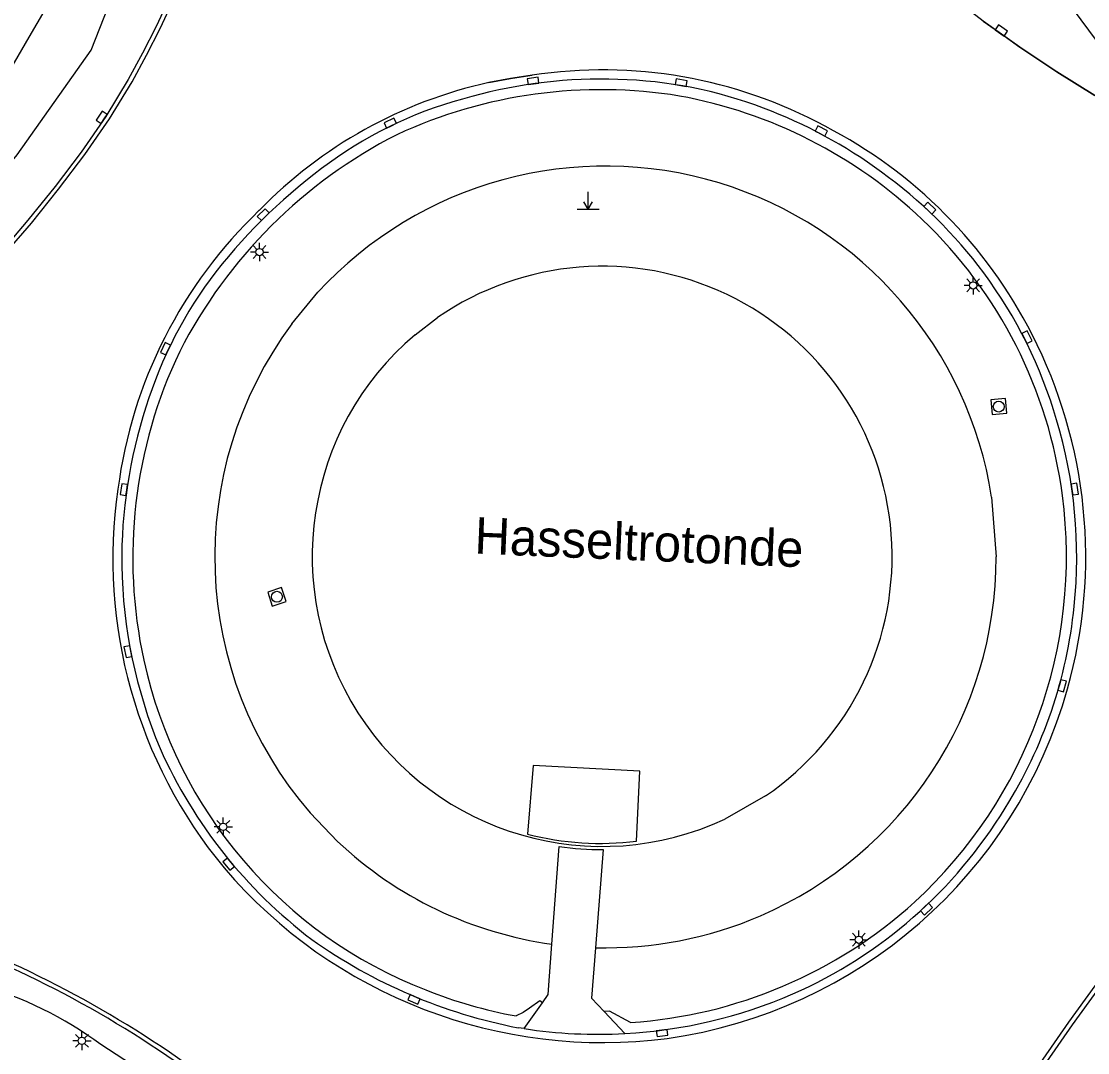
# Model space of a CAD drawing. Extents: x 132573 to 132944, y 398226 to 398676.
# Drawn here: x 132717.2 to 132790.1, y 398529.9 to 398600.4 of the extents above; entities that cross this region are included whole.
import ezdxf

# ---------------------------------------------------------------- set-up
doc = ezdxf.new("R2010")
doc.units = 0
for name, color, linetype in [('gg-anno-openbare ruimte label', 7, 'Continuous'), ('gg-knt-verharding', 7, 'Continuous'), ('gt-grn-groengrens', 7, 'Continuous'), ('gt-symb-kolk', 7, 'Continuous'), ('gt-symb-lichtmast', 7, 'Continuous'), ('gt-symb-markant object', 7, 'Continuous'), ('gt-symb-rioolschacht', 7, 'Continuous'), ('ir-asfa-asfalt arcering', 7, 'Continuous')]:
    doc.layers.add(name, color=color, linetype=linetype)

msp = doc.modelspace()

# ---------------------------------------------------------------- linework, layer by layer
at = {"layer": 'gg-knt-verharding'}
for p, q in [((132753.497, 398537.291), (132753.987, 398543.962)), ((132756.99, 398543.751), (132756.475, 398537.047)), ((132751.597, 398531.515), (132752.843, 398533.274)), ((132757.071, 398532.686), (132758.488, 398531.181)), ((132751.597, 398531.515), (132751.193, 398531.579))]:
    msp.add_line(p, q, dxfattribs=at)
for points in [[(132804.517, 398588.97), (132801.609, 398590.017), (132798.781, 398591.166), (132796.001, 398592.428), (132793.274, 398593.802), (132790.609, 398595.29), (132788.013, 398596.897), (132785.477, 398598.596), (132782.987, 398600.362), (132781.584, 398601.429), (132780.223, 398602.55), (132776.258, 398606.047), (132773.651, 398608.506), (132771.328, 398610.934), (132769.16, 398613.439), (132767.11, 398616.043), (132765.185, 398618.739), (132764.27, 398620.121), (132763.109, 398622.093)], [(132730.572, 398610.916), (132729.337, 398607.173), (132728.34, 398604.388), (132727.206, 398601.656), (132726.438, 398600.001), (132725.517, 398598.174), (132724.533, 398596.379), (132722.993, 398593.854), (132721.312, 398591.421), (132719.528, 398589.063), (132717.677, 398586.758), (132716.062, 398584.871), (132714.384, 398583.039), (132712.637, 398581.273), (132710.815, 398579.584), (132708.924, 398577.973), (132706.969, 398576.441), (132704.953, 398574.989), (132702.88, 398573.621), (132700.49, 398572.115), (132698.154, 398570.84)], [(132749.187, 398596.167), (132750.659, 398596.453), (132752.149, 398596.669)], [(132814.41, 398558.002), (132813.19, 398557.181), (132810.42, 398555.136), (132807.72, 398553), (132805.071, 398550.8), (132803.779, 398549.661), (132802.542, 398548.463), (132800.438, 398546.23), (132798.437, 398543.904), (132795.544, 398540.327), (132792.7, 398536.71), (132790.857, 398534.259), (132789.059, 398531.775), (132787.312, 398529.255), (132786.355, 398527.786)], [(132759.288, 398544.332), (132759.51, 398549.111), (132752.217, 398549.491), (132751.83, 398544.808)], [(132752.843, 398533.274), (132753.244, 398533.841), (132753.497, 398537.291)], [(132756.475, 398537.047), (132756.21, 398533.601), (132757.071, 398532.686)], [(132752.843, 398533.274), (132752.672, 398533.406), (132751.97, 398532.907), (132751.522, 398532.616), (132751.046, 398532.384)], [(132758.876, 398531.937), (132757.44, 398532.721), (132757.071, 398532.686)]]:
    msp.add_lwpolyline(points, dxfattribs=at)
for centre, radius, start, end in [((132756.963, 398565.093), 31.941, 61.55928, 98.66902), ((132756.793, 398563.614), 32.79, 87.86658, 105.50115), ((132757.247, 398566.313), 30.078, 69.13326, 88.53946), ((132755.885, 398565.654), 31.239, 102.38087, 135.79032), ((132756.864, 398562.478), 33.205, 80.72629, 114.86044), ((132754.788, 398567.933), 28.103, 103.91356, 125.9423), ((132756.378, 398563.229), 32.548, 46.42276, 79.66833), ((132756.131, 398562.938), 33.629, 53.74079, 69.4045), ((132757.206, 398564.149), 32.662, 26.95424, 62.72263), ((132758.332, 398562.293), 34.014, 116.97416, 152.91388), ((132761.111, 398559.079), 38.983, 125.82863, 141.69357), ((132757.041, 398563.771), 32.42, 36.74989, 54.1663), ((132755.558, 398564.266), 31.996, 133.59843, 172.59731), ((132756.947, 398563.827), 31.722, 7.47814, 46.42253), ((132754.355, 398565.072), 29.971, 142.67745, 162.6865), ((132757.225, 398564.118), 32.066, 16.30578, 36.44965), ((132756.672, 398563.749), 33.319, 344.32764, 27.15166), ((132757.447, 398563.676), 32.606, 154.37004, 192.37204), ((132758.321, 398563.462), 34.238, 162.08964, 180.4849), ((132756.95, 398563.784), 32.425, 353.96761, 16.73652), ((132756.554, 398563.601), 33.074, 171.67866, 219.6413), ((132756.62, 398563.783), 32.052, 312.57762, 7.48168), ((132758.237, 398563.806), 34.159, 181.06369, 202.62542), ((132757.564, 398563.492), 31.784, 327.87595, 354.37362), ((132756.244, 398563.398), 31.371, 192.34614, 248.76257), ((132756.768, 398563.757), 33.229, 277.98264, 344.26876), ((132757.191, 398564.248), 33.373, 204.01756, 232.94132), ((132756.99, 398563.356), 32.2, 293.76374, 328.62376), ((132756.79, 398563.859), 19.686, 255.40659, 277.28961), ((132756.863, 398563.421), 19.671, 261.59223, 270.36942), ((132756.974, 398564.606), 34.042, 220.49094, 277.44088), ((132756.775, 398563.908), 32.04, 273.76027, 312.22201), ((132685.962, 398469.092), 73.258, 52.01355, 69.15229), ((132758.044, 398567.112), 36.188, 234.59652, 259.08765), ((132756.777, 398563.923), 32.055, 248.21425, 259.70114), ((132756.655, 398564.662), 33.532, 273.13325, 293.38841), ((132756.655, 398564.616), 33.485, 261.31219, 273.13802)]:
    msp.add_arc(centre, radius, start, end, dxfattribs=at)
at = {"layer": 'gt-grn-groengrens'}
for p, q in [((132735.719, 398579.683), (132737.501, 398581.836)), ((132744.145, 398578.936), (132745.681, 398580.11)), ((132783.556, 398567.84), (132783.871, 398563.751)), ((132768.1, 398547.418), (132765.324, 398545.836)), ((132738.84, 398544.31), (132736.96, 398546.271))]:
    msp.add_line(p, q, dxfattribs=at)
for points in [[(132706.238, 398585.328), (132700.524, 398580.236), (132698.397, 398578.341), (132698.865, 398576.798), (132699.804, 398575.637), (132706.276, 398580.281), (132713.192, 398586.704), (132716.947, 398591.224), (132721.989, 398598.375), (132723.82, 398603.024), (132724.452, 398604.629), (132723.622, 398605.26), (132721.995, 398604.844), (132719.838, 398602.875), (132717.889, 398599.543), (132717.479, 398598.843), (132714.696, 398594.086), (132708.872, 398587.901), (132706.238, 398585.328)], [(132787.196, 398603.827), (132787.25, 398603.827), (132788.8, 398605.005), (132795.328, 398596.227), (132793.724, 398594.996), (132787.196, 398603.827)]]:
    msp.add_lwpolyline(points, dxfattribs=at)
for centre, radius, start, end in [((132757.159, 398563.751), 26.712, 8.80593, 137.38628), ((132756.936, 398563.795), 19.82, 304.28132, 124.60054), ((132757.157, 398563.75), 26.71, 143.37995, 220.87429), ((132756.931, 398563.791), 19.82, 130.1716, 295.05461), ((132757.158, 398563.751), 26.713, 293.35304, 0.00099), ((132757.157, 398563.747), 26.708, 226.69869, 262.1233), ((132757.157, 398563.764), 26.725, 268.53774, 293.34415), ((132707.466, 398509.992), 25.46, 53.38933, 74.3811), ((132737.747, 398545.177), 27.746, 207.46961, 245.73407), ((132666.873, 398441.22), 105.211, 47.06533, 57.98488)]:
    msp.add_arc(centre, radius, start, end, dxfattribs=at)
at = {"layer": 'gt-symb-kolk'}
for points in [[(132784.101, 398599.561), (132784.407, 398599.344), (132784.638, 398599.67), (132784.027, 398600.104), (132783.795, 398599.778), (132784.101, 398599.561)], [(132752.233, 398596.085), (132752.604, 398596.137), (132752.549, 398596.533), (132751.806, 398596.429), (132751.862, 398596.033), (132752.233, 398596.085)], [(132762.302, 398595.963), (132762.672, 398595.9), (132762.739, 398596.294), (132762, 398596.42), (132761.932, 398596.026), (132762.302, 398595.963)], [(132722.878, 398593.682), (132723.084, 398593.995), (132722.749, 398594.215), (132722.338, 398593.588), (132722.672, 398593.369), (132722.878, 398593.682)], [(132742.531, 398593.222), (132742.868, 398593.385), (132742.694, 398593.745), (132742.019, 398593.418), (132742.194, 398593.059), (132742.531, 398593.222)], [(132771.827, 398592.68), (132772.159, 398592.505), (132772.345, 398592.859), (132771.682, 398593.209), (132771.495, 398592.855), (132771.827, 398592.68)], [(132779.199, 398587.438), (132779.473, 398587.182), (132779.746, 398587.474), (132779.198, 398587.986), (132778.925, 398587.694), (132779.199, 398587.438)], [(132733.9, 398586.993), (132734.169, 398587.255), (132733.889, 398587.541), (132733.352, 398587.018), (132733.631, 398586.731), (132733.9, 398586.993)], [(132785.794, 398578.679), (132785.964, 398578.345), (132786.321, 398578.526), (132785.98, 398579.195), (132785.624, 398579.013), (132785.794, 398578.679)], [(132727.266, 398577.895), (132727.426, 398578.234), (132727.065, 398578.405), (132726.744, 398577.727), (132727.106, 398577.556), (132727.266, 398577.895)], [(132724.43, 398568.325), (132724.483, 398568.696), (132724.087, 398568.753), (132723.981, 398568.011), (132724.377, 398567.954), (132724.43, 398568.325)], [(132789.05, 398568.36), (132789.103, 398567.989), (132789.499, 398568.045), (132789.393, 398568.788), (132788.997, 398568.731), (132789.05, 398568.36)], [(132724.701, 398557.313), (132724.63, 398557.681), (132724.237, 398557.605), (132724.38, 398556.869), (132724.772, 398556.945), (132724.701, 398557.313)], [(132788.193, 398555.001), (132788.093, 398554.64), (132788.478, 398554.533), (132788.679, 398555.256), (132788.293, 398555.362), (132788.193, 398555.001)], [(132731.549, 398542.888), (132731.309, 398543.176), (132731.002, 398542.92), (132731.482, 398542.344), (132731.789, 398542.6), (132731.549, 398542.888)], [(132778.976, 398539.83), (132778.702, 398539.574), (132778.975, 398539.282), (132779.523, 398539.794), (132779.25, 398540.086), (132778.976, 398539.83)], [(132744.143, 398533.701), (132743.797, 398533.845), (132743.643, 398533.476), (132744.336, 398533.188), (132744.489, 398533.557), (132744.143, 398533.701)], [(132761.002, 398531.414), (132760.63, 398531.365), (132760.682, 398530.969), (132761.426, 398531.066), (132761.374, 398531.463), (132761.002, 398531.414)]]:
    msp.add_lwpolyline(points, dxfattribs=at)
at = {"layer": 'gt-symb-lichtmast'}
for p, q in [((132733.327, 398584.763), (132733.062, 398585.028)), ((132733.504, 398584.836), (132733.504, 398585.211)), ((132733.681, 398584.763), (132733.946, 398585.028)), ((132733.254, 398584.586), (132732.879, 398584.586)), ((132733.327, 398584.409), (132733.062, 398584.144)), ((132733.504, 398584.336), (132733.504, 398583.961)), ((132733.946, 398584.144), (132733.681, 398584.409)), ((132733.754, 398584.586), (132734.129, 398584.586)), ((132782.117, 398582.486), (132781.852, 398582.751)), ((132782.294, 398582.559), (132782.294, 398582.934)), ((132782.471, 398582.486), (132782.736, 398582.751)), ((132782.044, 398582.309), (132781.669, 398582.309)), ((132782.117, 398582.132), (132781.852, 398581.867)), ((132782.294, 398582.059), (132782.294, 398581.684)), ((132782.736, 398581.867), (132782.471, 398582.132)), ((132782.544, 398582.309), (132782.919, 398582.309)), ((132730.776, 398545.309), (132730.401, 398545.309)), ((132730.849, 398545.486), (132730.584, 398545.751)), ((132731.026, 398545.559), (132731.026, 398545.934)), ((132731.203, 398545.486), (132731.468, 398545.751)), ((132731.276, 398545.309), (132731.651, 398545.309)), ((132730.849, 398545.132), (132730.584, 398544.867)), ((132731.026, 398545.059), (132731.026, 398544.684)), ((132731.468, 398544.867), (132731.203, 398545.132)), ((132774.3, 398537.769), (132774.035, 398538.034)), ((132774.477, 398537.842), (132774.477, 398538.217)), ((132774.654, 398537.769), (132774.919, 398538.034)), ((132774.227, 398537.592), (132773.852, 398537.592)), ((132774.3, 398537.415), (132774.035, 398537.15)), ((132774.477, 398537.342), (132774.477, 398536.967)), ((132774.919, 398537.15), (132774.654, 398537.415)), ((132774.727, 398537.592), (132775.102, 398537.592)), ((132721.112, 398530.681), (132720.737, 398530.681)), ((132721.185, 398530.858), (132720.92, 398531.123)), ((132721.362, 398530.931), (132721.362, 398531.306)), ((132721.539, 398530.858), (132721.804, 398531.123)), ((132721.612, 398530.681), (132721.987, 398530.681)), ((132721.185, 398530.504), (132720.92, 398530.239)), ((132721.362, 398530.431), (132721.362, 398530.056)), ((132721.804, 398530.239), (132721.539, 398530.504))]:
    msp.add_line(p, q, dxfattribs=at)
for centre in [(132733.504, 398584.586), (132782.294, 398582.309), (132731.026, 398545.309), (132774.477, 398537.592), (132721.362, 398530.681)]:
    msp.add_circle(centre, 0.25, dxfattribs=at)
at = {"layer": 'gt-symb-markant object'}
for p, q in [((132755.978, 398587.506), (132755.978, 398588.706)), ((132755.978, 398587.506), (132755.678, 398588.026)), ((132755.978, 398587.506), (132756.278, 398588.026)), ((132755.228, 398587.506), (132756.728, 398587.506))]:
    msp.add_line(p, q, dxfattribs=at)
at = {"layer": 'gt-symb-rioolschacht'}
for points in [[(132784.494, 398574.574), (132783.499, 398574.477), (132783.596, 398573.482), (132784.591, 398573.579)], [(132734.38, 398560.394), (132735.329, 398560.709), (132735.014, 398561.658), (132734.065, 398561.343)]]:
    msp.add_lwpolyline(points, close=True, dxfattribs=at)
for centre in [(132784.045, 398574.028), (132734.697, 398561.026)]:
    msp.add_circle(centre, 0.375, dxfattribs=at)
at = {"layer": 'ir-asfa-asfalt arcering'}
for points in [[(132716.287, 398584.672), (132717.908, 398586.566), (132719.765, 398588.879), (132721.555, 398591.245), (132723.245, 398593.69), (132724.793, 398596.229), (132725.783, 398598.034), (132726.708, 398599.87), (132727.481, 398601.535), (132728.62, 398604.28), (132729.621, 398607.075), (132730.857, 398610.822), (132730.86, 398610.831), (132730.919, 398611.032), (132739.76, 398613.997), (132737.286, 398604.502), (132737.58, 398604.441), (132740.628, 398605.656)], [(132782.987, 398600.362), (132783.8, 398599.785), (132783.795, 398599.778), (132784.407, 398599.344), (132784.412, 398599.351), (132785.477, 398598.596), (132788.013, 398596.897), (132790.609, 398595.29)], [(132752.149, 398596.669), (132750.659, 398596.453), (132749.187, 398596.167)], [(132801.672, 398563.795), (132801.612, 398562.102), (132807.36, 398565.541), (132811.34, 398567.758), (132814.317, 398558.297), (132814.253, 398558.258), (132814.243, 398558.251), (132813.017, 398557.426), (132810.238, 398555.374), (132807.531, 398553.233), (132804.876, 398551.028), (132803.575, 398549.881), (132802.328, 398548.674), (132800.215, 398546.431), (132798.207, 398544.096), (132795.309, 398540.514), (132792.462, 398536.893), (132790.616, 398534.437), (132788.814, 398531.948), (132787.063, 398529.422), (132786.105, 398527.952)]]:
    msp.add_lwpolyline(points, dxfattribs=at)
for centre, radius, start, end in [((132756.963, 398565.093), 31.941, 61.55928, 98.66902), ((132755.885, 398565.654), 31.239, 102.38087, 135.79032), ((132757.206, 398564.149), 32.662, 26.95424, 62.72263), ((132755.558, 398564.266), 31.996, 133.59843, 172.59731), ((132756.672, 398563.749), 33.319, 344.32764, 27.15166), ((132756.554, 398563.601), 33.074, 171.67866, 219.6413), ((132756.768, 398563.757), 33.229, 277.98264, 344.26876), ((132756.974, 398564.606), 34.042, 220.49094, 277.44088), ((132685.962, 398469.092), 73.558, 52.01355, 69.15229)]:
    msp.add_arc(centre, radius, start, end, dxfattribs=at)

# ---------------------------------------------------------------- texts
at = {"layer": 'gg-anno-openbare ruimte label'}
msp.add_text('Hasseltrotonde', height=2.5, rotation=357.6, dxfattribs=at).set_placement((132748.175, 398563.985))

doc.saveas('drawing.dxf')
